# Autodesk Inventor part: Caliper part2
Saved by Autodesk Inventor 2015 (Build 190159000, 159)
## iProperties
Created: 2015-04
Part Number: Caliper part2
Material: Generic
Document SubType Name: Modeling
Designer: Gabriel Cabellos
Density: 1 g/cm^3
Appearance: Default
Author: Gabriel Cabellos
Sending System: SolidWorks 2011
Last Author: Pets
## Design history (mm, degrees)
node "Caliper part2.ipt1"
node "Cut-Extrude14"
node "Base1"
